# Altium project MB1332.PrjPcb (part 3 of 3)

## Sheet STLink_V3E_SWD.SchDoc: ST-LINK-V3E SWD
size A3; Date: Not used; ApprovedBy: Not used; CheckedBy: Not used; Author: Not used; CompanyName: STMicroelectronics; DrawnBy: Not used; Engineer: Not used; Organization: Not used; Address1: Not used; Address2: Not used; Address3: Not used; Address4: Not used; DocumentNumber: Not used; Revision: Not used; SheetNumber: 17; SheetTotal: 17
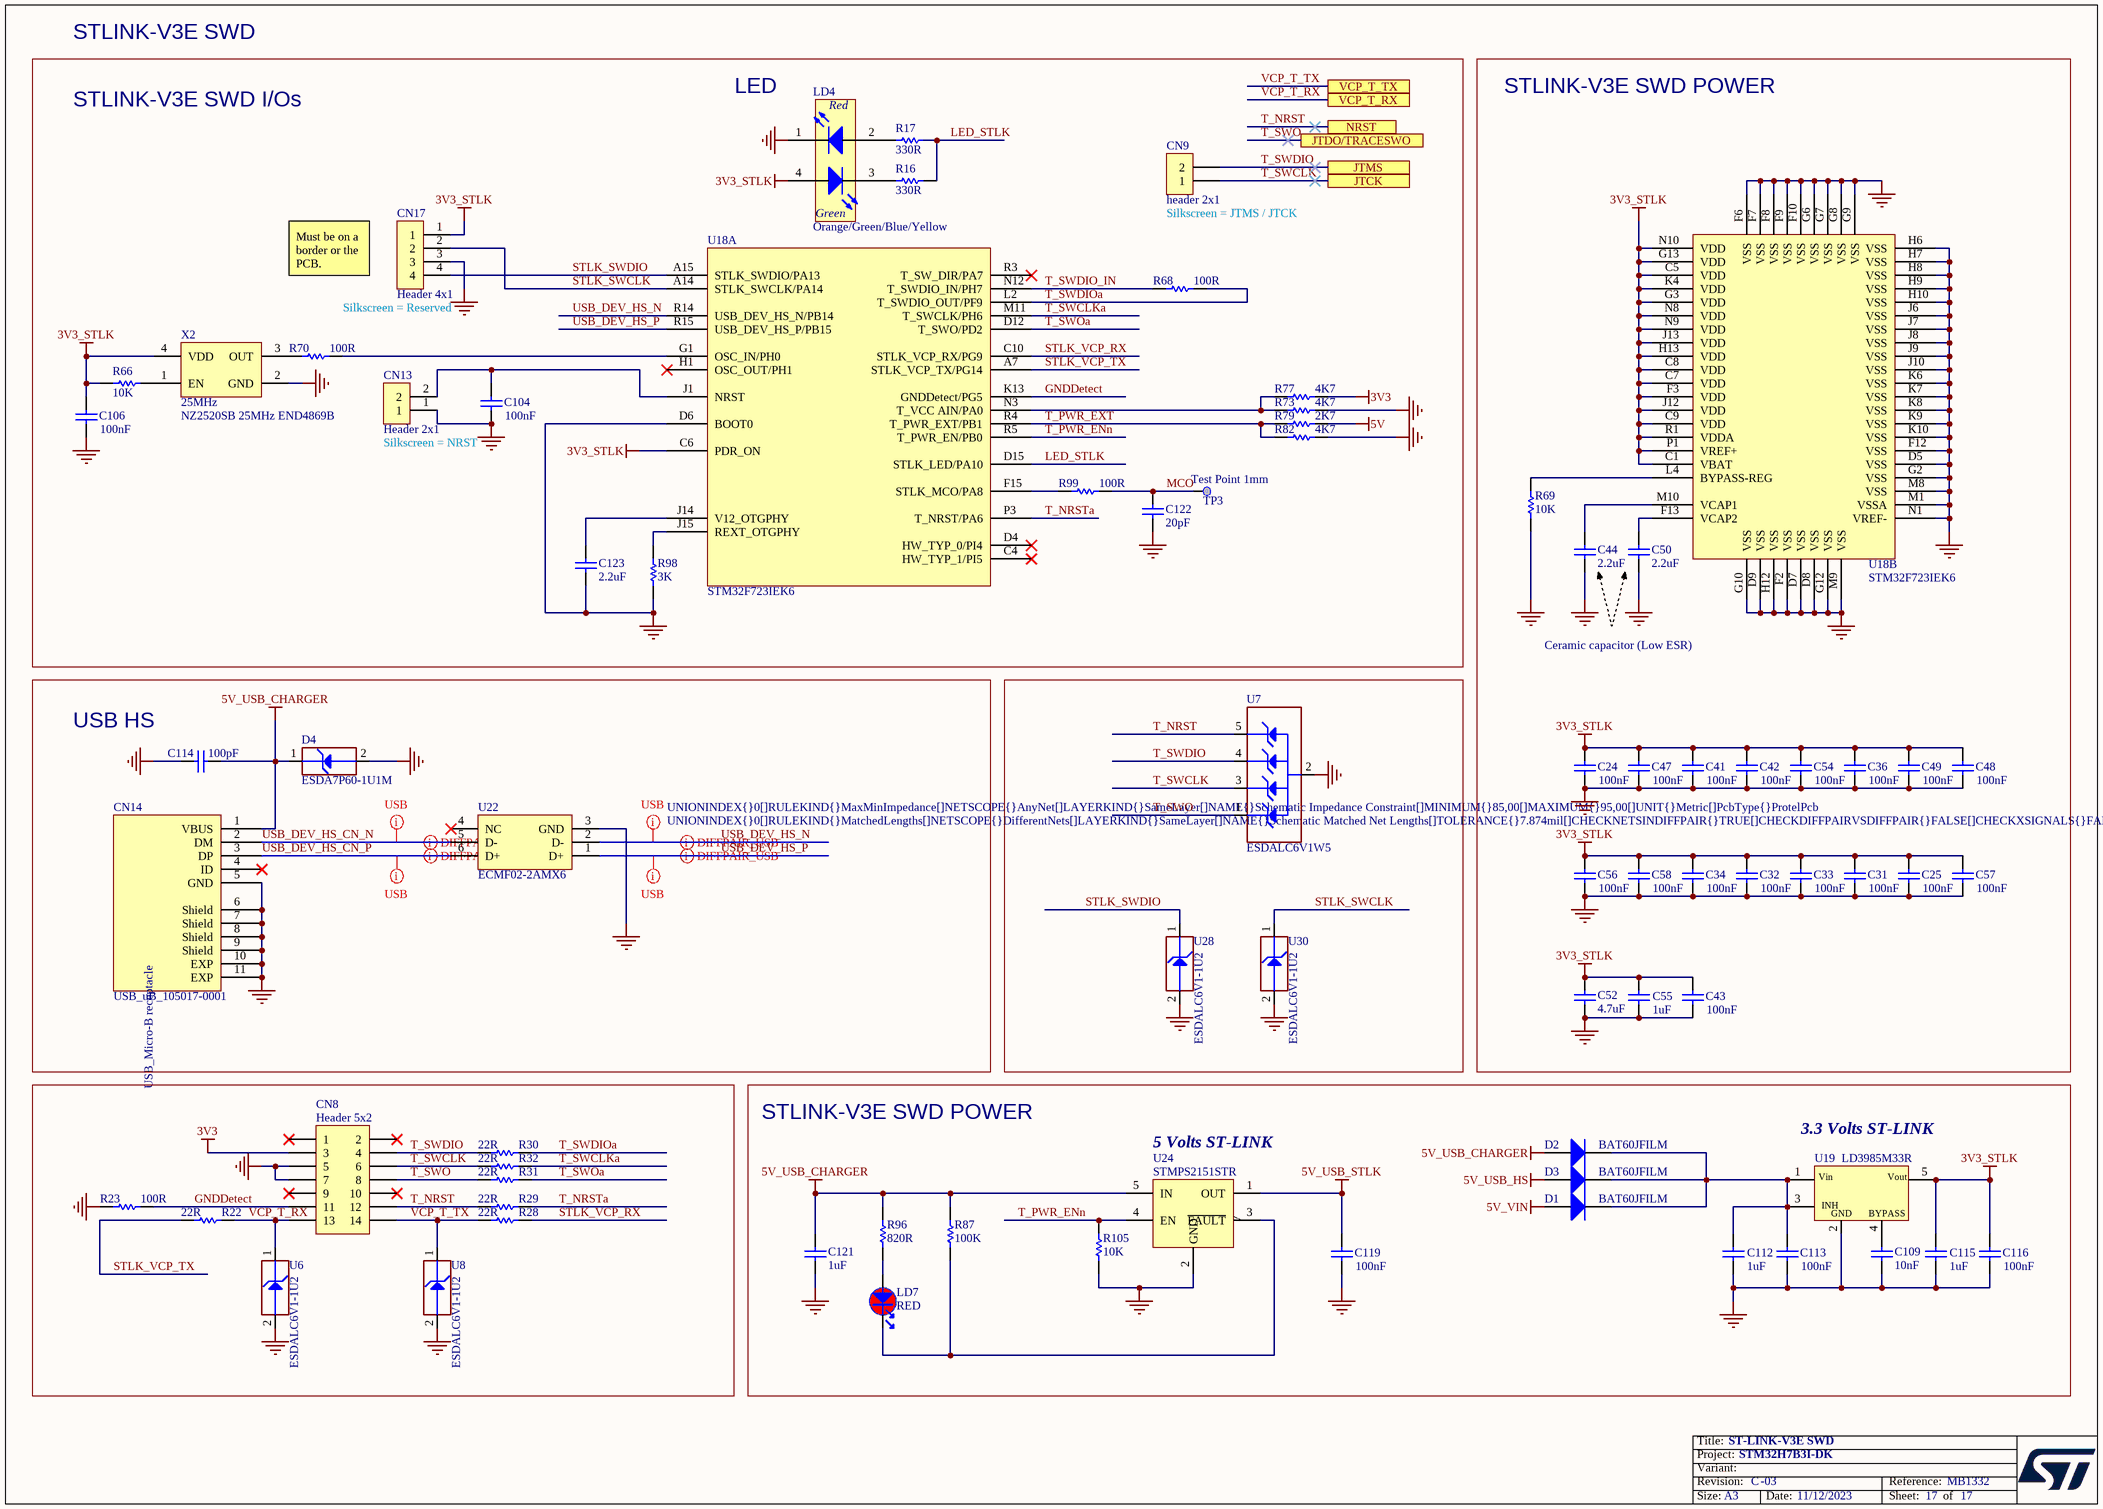
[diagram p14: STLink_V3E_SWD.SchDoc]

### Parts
C24  value 100nF  [C0402]  (hidden comment: Capacitor)
C25  value 100nF  [C0402]  (hidden comment: Capacitor)
C31  value 100nF  [C0402]  (hidden comment: Capacitor)
C32  value 100nF  [C0402]  (hidden comment: Capacitor)
C33  value 100nF  [C0402]  (hidden comment: Capacitor)
C34  value 100nF  [C0402]  (hidden comment: Capacitor)
C36  value 100nF  [C0402]  (hidden comment: Capacitor)
C41  value 100nF  [C0402]  (hidden comment: Capacitor)
C42  value 100nF  [C0402]  (hidden comment: Capacitor)
C43  value 100nF  [C0402]  (hidden comment: Capacitor)
C44  value 2.2uF  [C0603]  (hidden comment: Capacitor)
C47  value 100nF  [C0402]  (hidden comment: Capacitor)
C48  value 100nF  [C0402]  (hidden comment: Capacitor)
C49  value 100nF  [C0402]  (hidden comment: Capacitor)
C50  value 2.2uF  [C0603]  (hidden comment: Capacitor)
C52  value 4.7uF  [C0603]  (hidden comment: Capacitor)
C54  value 100nF  [C0402]  (hidden comment: Capacitor)
C55  value 1uF  [C0603]  (hidden comment: Capacitor)
C56  value 100nF  [C0402]  (hidden comment: Capacitor)
C57  value 100nF  [C0402]  (hidden comment: Capacitor)
C58  value 100nF  [C0402]  (hidden comment: Capacitor)
C104  value 100nF  [C0402]  (hidden comment: Capacitor)
C106  value 100nF  [C0402]  (hidden comment: Capacitor)
C109  value 10nF  [C0402]  (hidden comment: Capacitor)
C112  value 1uF  [C0603]  (hidden comment: Capacitor)
C113  value 100nF  [C0402]  (hidden comment: Capacitor)
C114  value 100pF  [C0402]  (hidden comment: Capacitor)
C115  value 1uF  [C0603]  (hidden comment: Capacitor)
C116  value 100nF  [C0402]  (hidden comment: Capacitor)
C119  value 100nF  [C0402]  (hidden comment: Capacitor)
C121  value 1uF  [C0603]  (hidden comment: Capacitor)
C122  value 20pF  [C0402]  (hidden comment: Capacitor)
C123  value 2.2uF  [C0603]  (hidden comment: Capacitor)
CN8  value Header 5x2  [CON_STDC14_Receiver_MEDIUM_WITH_MIPI10_3D]  (hidden comment: Header 7x2)
CN9  Header 2x1  [CON_988-JIUBABA_PHFS25-11-02-G0B115-T-1]
CN13  Header 2x1  [CON_SAMTEC_TSW-102-07-G-S]
CN14  value USB_uB_105017-0001  [CON_USBMICROB_MOLEX_105017-0001_H2P90]  (hidden comment: USB_uB_105017.0001)
CN17  Header 4x1  [CON_SAMTEC_TSW-104-07-G-S]
D1  BAT60JFILM  [DIO_SOD323]
D2  BAT60JFILM  [DIO_SOD323]
D3  BAT60JFILM  [DIO_SOD323]
D4  value ESDA7P60-1U1M  [ESD_QFN2_1P6X1_P125]  (hidden comment: ESD-TRANSIL)
LD4  value Orange/Green/Blue/Yellow  [LED_BI-GR_HSMF-A201-A00J1]  (hidden comment: LD_BICOLOR_CMS)
LD7  value RED  [LED_0603_VISHAY_VLMS1300-GS08_RED_1A2K_H0P8]  (hidden comment: LED_red)
R16  value 330R  [R0603]  (hidden comment: Resistor)
R17  value 330R  [R0603]  (hidden comment: Resistor)
R22  value 22R  [R0603]  (hidden comment: Resistor)
R23  value 100R  [R0402]  (hidden comment: Resistor)
R28  value 22R  [R0603]  (hidden comment: Resistor)
R29  value 22R  [R0603]  (hidden comment: Resistor)
R30  value 22R  [R0603]  (hidden comment: Resistor)
R31  value 22R  [R0603]  (hidden comment: Resistor)
R32  value 22R  [R0603]  (hidden comment: Resistor)
R66  value 10K  [R0402]  (hidden comment: Resistor)
R68  value 100R  [R0402]  (hidden comment: Resistor)
R69  value 10K  [R0402]  (hidden comment: Resistor)
R70  value 100R  [R0402]  (hidden comment: Resistor)
R73  value 4K7  [R0402]  (hidden comment: Resistor)
R77  value 4K7  [R0402]  (hidden comment: Resistor)
R79  value 2K7  [R0402]  (hidden comment: Resistor)
R82  value 4K7  [R0402]  (hidden comment: Resistor)
R87  value 100K  [R0402]  (hidden comment: Resistor)
R96  value 820R  [R0402]  (hidden comment: Resistor)
R98  value 3K  [R0402]  (hidden comment: Resistor)
R99  value 100R  [R0402]  (hidden comment: Resistor)
R105  value 10K  [R0402]  (hidden comment: Resistor)
TP3  value Test Point 1mm  [TP_SMD_1MM]  (hidden comment: Test Point)  (no BOM)
U6  value ESDALC6V1-1U2  [ESD_ST0201]  (hidden comment: ESD-TRANSIL)
U7  ESDALC6V1W5  [ESD_SOT323-5L]
U8  value ESDALC6V1-1U2  [ESD_ST0201]  (hidden comment: ESD-TRANSIL)
U18  value STM32F723IEK6  [ICC_UFBGA201_176+25_10X10_P065]  (hidden comment: ST-LINKV3E_SWD)  (parts A,B of 2)
U19  LD3985M33R  [REG_SOT23-5L]
U22  ECMF02-2AMX6  [ESD_QFN-6L_1P7X1P5_P050]
U24  STMPS2151STR  [MOS_SOT23-5L]
U28  value ESDALC6V1-1U2  [ESD_ST0201]  (hidden comment: ESD-TRANSIL)
U30  value ESDALC6V1-1U2  [ESD_ST0201]  (hidden comment: ESD-TRANSIL)
X2  value 25MHz  [OSC_NDK_NZ2520SB_4P]  (hidden comment: OSCILLATOR_4_PINS)

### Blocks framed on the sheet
STLINK-V3E SWD POWER: C24 C25 C31-C34 C36 C41-C44 C47-C50 C52 C54-C58 R69 U18
USB HS: C114 CN14 D4 U22
STLINK-V3E SWD POWER: C109 C112 C113 C115 C116 C119 C121 D1-D3 LD7 R87 R96 R105 U19 U24

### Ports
JTCK, JTDO/TRACESWO, JTMS, NRST, VCP_T_RX, VCP_T_TX

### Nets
3V3: CN8.3 R77.2
3V3_STLK: C24.1 C25.1 C31.1 C32.1 C33.1 C34.1 C36.1 C41.1 C42.1 C43.1 C47.1 C48.1 C49.1 C52.2 C54.1 C55.2 C56.1 C57.1 C58.1 C106.1 C115.2 C116.1 CN17.1 LD4.4(YellowGreen_anode) R66.1 U18.C1(VBAT) U18.C5(VDD) U18.C6(PDR_ON) U18.C7(VDD) U18.C8(VDD) U18.C9(VDD) U18.F3(VDD) U18.G3(VDD) U18.G13(VDD) U18.H13(VDD) U18.J12(VDD) U18.J13(VDD) U18.K4(VDD) U18.N8(VDD) U18.N9(VDD) U18.N10(VDD) U18.P1(VREF+) U18.R1(VDDA) U19.5(Vout) X2.4(VDD)
5V: R79.1
5V_USB_CHARGER: C114.2 C121.2 CN14.1(VBUS) D2.1(A) D4.1(IO1) R87.1 R96.2 U24.5(IN)
5V_USB_HS: D3.1(A)
5V_USB_STLK: C119.1 U24.1(OUT)
5V_VIN: D1.1(A)
GND: C24.2 C25.2 C31.2 C32.2 C33.2 C34.2 C36.2 C41.2 C42.2 C43.2 C44.1 C47.2 C48.2 C49.2 C50.1 C52.1 C54.2 C55.1 C56.2 C57.2 C58.2 C104.2 C106.2 C109.1 C112.1 C113.2 C114.1 C115.1 C116.2 C119.2 C121.1 C122.1 C123.1 CN8.5 CN8.7 CN13.1 CN14.5(GND) CN14.6(Shield) CN14.7(Shield) CN14.8(Shield) CN14.9(Shield) CN14.10(EXP) CN14.11(EXP) CN17.3 D4.2(GND) LD4.1(RED_cathode) R23.1 R69.1 R73.2 R82.1 R98.1 R105.2 U6.2(GND) U7.2(GND) U8.2(GND) U18.D5(VSS) U18.D6(BOOT0) U18.D7(VSS) U18.D8(VSS) U18.D9(VSS) U18.F2(VSS) U18.F6(VSS) U18.F7(VSS) U18.F8(VSS) U18.F9(VSS) U18.F10(VSS) U18.F12(VSS) U18.G2(VSS) U18.G6(VSS) U18.G7(VSS) U18.G8(VSS) U18.G9(VSS) U18.G10(VSS) U18.G12(VSS) U18.H6(VSS) U18.H7(VSS) U18.H8(VSS) U18.H9(VSS) U18.H10(VSS) U18.H12(VSS) U18.J6(VSS) U18.J7(VSS) U18.J8(VSS) U18.J9(VSS) U18.J10(VSS) U18.K6(VSS) U18.K7(VSS) U18.K8(VSS) U18.K9(VSS) U18.K10(VSS) U18.M1(VSSA) U18.M8(VSS) U18.M9(VSS) U18.N1(VREF-) U19.2(GND) U22.3(GND) U24.2(GND) U28.2(GND) U30.2(GND) X2.2(GND)
GNDDetect: CN8.11 R23.2 U18.K13(GNDDetect/PG5)
LED_STLK: R16.2 R17.2 U18.D15(STLK_LED/PA10)
MCO: C122.2 R99.2 TP3.1
STLK_SWCLK: CN17.2 U18.A14(STLK_SWCLK/PA14) U30.1(IO1)
STLK_SWDIO: CN17.4 U18.A15(STLK_SWDIO/PA13) U28.1(IO1)
STLK_VCP_RX: R28.2 U18.C10(STLK_VCP_RX/PG9)
STLK_VCP_TX: R22.2 U18.A7(STLK_VCP_TX/PG14)
T_NRST: CN8.12 R29.1 U7.5(IO4) ; port NRST
T_NRSTa: R29.2 U18.P3(T_NRST/PA6)
T_PWR_ENn: R105.1 U18.R5(T_PWR_EN/PB0) U24.4(EN)
T_PWR_EXT: R79.2 R82.2 U18.R4(T_PWR_EXT/PB1)
T_SWCLK: CN8.6 CN9.1 R32.1 U7.3(IO2) ; port JTCK
T_SWCLKa: R32.2 U18.M11(T_SWCLK/PH6)
T_SWDIO: CN8.4 CN9.2 R30.1 U7.4(IO3) ; port JTMS
T_SWDIO_IN: R68.1 U18.N12(T_SWDIO_IN/PH7)
T_SWDIOa: R30.2 R68.2 U18.L2(T_SWDIO_OUT/PF9)
T_SWO: CN8.8 R31.1 U7.1(IO1) ; port JTDO/TRACESWO
T_SWOa: R31.2 U18.D12(T_SWO/PD2)
USB_DEV_HS_CN_N: CN14.2(DM) U22.5(D-)
USB_DEV_HS_CN_P: CN14.3(DP) U22.6(D+)
USB_DEV_HS_N: U18.R14(USB_DEV_HS_N/PB14) U22.2(D-)
USB_DEV_HS_P: U18.R15(USB_DEV_HS_P/PB15) U22.1(D+)
VCP_T_RX: CN8.13 R22.1 U6.1(IO1) ; port VCP_T_RX
VCP_T_TX: CN8.14 R28.1 U8.1(IO1) ; port VCP_T_TX
NetC44_2: C44.2 U18.M10(VCAP1)
NetC50_2: C50.2 U18.F13(VCAP2)
NetC104_1: C104.1 CN13.2 U18.J1(NRST)
NetC109_2: C109.2 U19.4(BYPASS)
NetC112_2: C112.2 C113.1 D1.2(K) D2.2(K) D3.2(K) U19.1(Vin) U19.3(CE)
NetC123_2: C123.2 U18.J14(V12_OTGPHY)
NetLD4_2: LD4.2(Red_anode) R17.1
NetLD4_3: LD4.3(YellowGreen_cathode) R16.1
NetLD7_1: LD7.1 R96.1
NetLD7_2: LD7.2 R87.2 U24.3(~{FAULT})
NetR66_2: R66.2 X2.1(EN)
NetR69_2: R69.2 U18.L4(BYPASS-REG)
NetR70_1: R70.1 X2.3(OUT)
NetR70_2: R70.2 U18.G1(OSC_IN/PH0)
NetR73_1: R73.1 R77.1 U18.N3(T_VCC_AIN/PA0)
NetR98_2: R98.2 U18.J15(REXT_OTGPHY)
NetR99_1: R99.1 U18.F15(STLK_MCO/PA8)

Not connected (* = marked no-connect by the designer): CN8 1* 2* 9* 10*; CN14 4(ID)*; U18 C4(HW_TYP_1/PI5)* D4(HW_TYP_0/PI4)* H1(OSC_OUT/PH1)* R3(T_SW_DIR/PA7)*; U22 4(NC)*

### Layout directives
differential pair; rule Impedance Constraint [Min = 85.00    Max = 95.00    ]: USB_DEV_HS_CN_N, USB_DEV_HS_CN_P, USB_DEV_HS_N, USB_DEV_HS_P
rule Undefined; rule Matched Net Lengths [Tolerance = 0.2mm]; rule Impedance Constraint [Min = 85.00    Max = 95.00    ]: USB_DEV_HS_CN_N, USB_DEV_HS_CN_P, USB_DEV_HS_N, USB_DEV_HS_P

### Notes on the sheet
- STLINK-V3E SWD
- STLINK-V3E SWD I/Os
- LED
- (near CN9) Silkscreen = JTMS / JTCK
- Must be on a border or the PCB.
- Silkscreen = Reserved
- (near X2) NZ2520SB 25MHz END4869B
- Silkscreen = NRST
- Ceramic capacitor (Low ESR)
- (near U24) 5 Volts ST-LINK
- (near U19) 3.3 Volts ST-LINK

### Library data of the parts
C24 C25 C31-C34 C36 C41-C43 C47-C49 C54 C56-C58 C104 C106 C113 C116 C119 = MCD-00006: Capacitor, MLCC, 100nF, 16V, X7R, +/-10%, 0402, T=0.5mm; Manufacturer_Part_Number: CC0402KRX7R7BB104; Manufacturer: YAGEO; Part_Preference: Recommended; Partial_Alternate_Internal_Part_Number: MCD-03299; Component_Country_Of_Origin: China; ID: 2474; Order_Code_RS: 9402047; ShowFields: YES
C44 C50 C123 = MCD-00012: Capacitor, MLCC, 2.2uF, 10V, X5R, 10%, 0603, T=0,8mm; Manufacturer_Part_Number: CC0603KRX5R6BB225; Manufacturer: YAGEO; Alternate_Manufacturer_Part_Number: C0603C225K8PACTU; Alternate_Manufacturer: KEMET; BMS_Part_Number: 9142010; Part_Preference: Recommended; Partial_Alternate_Internal_Part_Number: MCD-00551; Provided_By: SUBCO; Component_Country_Of_Origin: China; ID: 2467; Order_Code_RS: 2370679; ShowFields: YES
C52 = MCD-00009: Capacitor, MLCC, 4.7uF, 16V, X5R, 10%, 0603, T=0.8mm; Manufacturer_Part_Number: CC0603KRX5R7BB475; Manufacturer: YAGEO; Part_Preference: Recommended; Partial_Alternate_Internal_Part_Number: MCD-03565; Provided_By: SUBCO; Alternate_EMS: A; Component_Country_Of_Origin: China; ID: 2471; ShowFields: YES
C55 C112 C115 C121 = MCD-00010: Capacitor, MLCC, 1uF, 16V, X5R, 10%, 0603, T=0,8mm; Manufacturer_Part_Number: CC0603KRX5R7BB105; Manufacturer: YAGEO; Part_Preference: Recommended; Provided_By: SUBCO; Component_Country_Of_Origin: China; ID: 2470; Order_Code_RS: 2370680; ShowFields: YES
C109 = MCD-00011: Capacitor, MLCC, 10nF, 16V, X7R, 10%, 0402, T=0.5mm; Manufacturer_Part_Number: CC0402KRX7R7BB103; Manufacturer: YAGEO; Part_Preference: Recommended; Provided_By: SUBCO; Component_Country_Of_Origin: China; ID: 2469; Order_Code_RS: 3019275; ShowFields: YES
C114 = MCD-00205: Capacitor, MLCC, 100pF, 50V, NPO, 5%, 0402, T=0,5mm; Manufacturer_Part_Number: CC0402JRNPO9BN101; Manufacturer: YAGEO; Part_Preference: Recommended; Provided_By: SUBCO; Component_Country_Of_Origin: China; ID: 2658; ShowFields: YES
C122 = MCD-00016: Capacitor, MLCC, 20pF, 50V, NPO, 5%, 0402, T=0,5mm; Manufacturer_Part_Number: CC0402JRNPO9BN200; Manufacturer: YAGEO; Part_Preference: Recommended; Provided_By: SUBCO; Component_Country_Of_Origin: China; ID: 2479; ShowFields: YES
CN8 = MCD-01226: Header 5x2, 1.27mm, Dual row, Straight, Surface mount, vertical male connector. 3.05mm lead. Mates with FFSD connector. Footprint compatible with FTSH-107-01-L-DV,-K,-A,-P,-ES (STDC14 MEDIUM); Manufacturer_Part_Number: FTSH-105-01-L-DV-K; Manufacturer: SAMTEC; Part_Preference: Recommended; Partial_Alternate_Internal_Part_Number: MCD-02956; Provided_By: SUBCO; Component_Country_Of_Origin: China, Costa Rica, Malaysia, USA, Vietnam; ID: 3265; Order_Code_RS: 159-2332; ShowFields: YES
CN9 = MCD-00314: Header, 2x1, 2.54mm, VR, TH, Height 6mm/3mm; Part_Type: Connector; Manufacturer_Part_Number: PHFS25-11-02-G0B115-T-1; Manufacturer: JIUBABA; Part_Preference: Alternate; Provided_By: SUBCO; Alternate_EMS: A; Component_Country_Of_Origin: Unknown; ID: 2554; ShowFields: YES
CN13 = MCD-00032: Header, 2x1, 2,54mm, VR, TH, Height 5.84mm/2.54mm; Part_Type: Connector; Manufacturer_Part_Number: TSW-102-07-G-S; Manufacturer: SAMTEC; Alternate_Manufacturer_Part_Number: 313102S111116; Alternate_Manufacturer: JIUBABA; Part_Preference: Recommended; Component_Country_Of_Origin: China, Costa Rica, Malaysia, USA, Vietnam; ID: 2484; Order_Code_RS: 2505044; ShowFields: YES
CN14 = MCD-00028: USB-MICRO-B, 0.65mm, RA, SMT, Bottom Mount,; Manufacturer_Part_Number: 1050170001; Manufacturer: MOLEX; Part_Type: Connector; Part_Preference: Recommended; Provided_By: SUBCO; Component_Country_Of_Origin: Unknown; ID: 2489; Order_Code_RS: 2293836; ShowFields: YES
CN17 = MCD-00029: Header, 4x1, 2,54mm, VR, TH, Height 5.84mm/2.54mm; Manufacturer_Part_Number: TSW-104-07-G-S; Manufacturer: SAMTEC; Part_Type: Connector; Part_Preference: Recommended; Component_Country_Of_Origin: China, Costa Rica, Malaysia, USA, Vietnam; ID: 2487; Order_Code_RS: 2667450; ShowFields: YES
D1-D3 = MCD-00034: Manufacturer: STMICROELECTRONICS; Part_Type: Diode; BMS_Part_Number: 9151097; Manufacturer_HQ_COO: EU; Part_Preference: Recommended; Provided_By: SUBCO with ST control; Component_Country_Of_Origin: China; ID: 2483; Order_Code_RS: 714-6879; ShowFields: YES
D4 = MCD-00251: High power transient voltage suppressor, 7V breakdown; Part_Type: Diode; Manufacturer: STMICROELECTRONICS; BMS_Part_Number: 9179042; Manufacturer_HQ_COO: EU; Part_Preference: Recommended; Provided_By: SUBCO with ST control; Component_Country_Of_Origin: China; ID: 2618; Order_Code_RS: 110-6381; ShowFields: YES
LD4 = MCD-02402: LED Multicolor, Orange/Green/Blue/Yellow, 2V, 20mA, 4-PLCC; Part_Type: Display; Manufacturer_Part_Number: 67-22SURSYGC/S530-A2/TR8; Manufacturer: EVERLIGHT; Part_Preference: Alternate; Full_Alternate_Internal_Part_Number: MCD-00051, MCD-02631; Alternate_EMS: C; ShowFields: YES; ID: 4508
LD7 = MCD-00587: LED Red, 0603 SMD, 2V Forward Voltage; Part_Type: Display; Manufacturer_Part_Number: VLMS1300-GS08; Manufacturer: VISHAY; Alternate_Manufacturer_Part_Number: LS Q976-NR-1; Alternate_Manufacturer: OSRAM OPTO SEMICONDUCTORS; Full_Alternate_Internal_Part_Number: MCD-02401; Part_Preference: Recommended; Provided_By: SUBCO; Component_Country_Of_Origin: China; ID: 3154; ShowFields: YES
R16 R17 = MCD-00197: Resistor,330R,0603,1%,1/10W; Manufacturer_Part_Number: RC0603FR-07330RL; Manufacturer: YAGEO; BMS_Part_Number: 9129729; Part_Preference: Recommended; Provided_By: SUBCO; Component_Country_Of_Origin: China; ID: 2672; ShowFields: YES
R22 R28-R32 = MCD-00066: Resistor,22R,0603,1%,1/10W; Manufacturer_Part_Number: RC0603FR-0722RL; Manufacturer: YAGEO; Part_Preference: Recommended; Provided_By: SUBCO; Component_Country_Of_Origin: China; ID: 2530; Order_Code_RS: 9238280; ShowFields: YES
R23 R68 R70 R99 = MCD-00067: Resistor, 100R, 0402, +/- 1%, 1/16W; Manufacturer_Part_Number: RC0402FR-07100RL; Manufacturer: YAGEO; Part_Preference: Recommended; Order_Code_RS: 9239111; Component_Country_Of_Origin: China; ShowFields: YES; ID: 2527
R66 R69 R105 = MCD-00053: Resistor,10K,0402,1%,1/16W; Manufacturer_Part_Number: RC0402FR-0710KL; Manufacturer: YAGEO; BMS_Part_Number: 9131590; Part_Preference: Recommended; Provided_By: SUBCO; Component_Country_Of_Origin: China; ID: 2539; Order_Code_RS: 9239359; ShowFields: YES
R73 R77 R82 = MCD-00065: Resistor,4K7,0402,1%,1/16W; Manufacturer_Part_Number: RC0402FR-074K7L; Manufacturer: YAGEO; Alternate_Manufacturer_Part_Number: RT0402FRE074K7L; Part_Preference: Recommended; Partial_Alternate_Internal_Part_Number: MCD-03300; Provided_By: SUBCO; Component_Country_Of_Origin: China; ID: 2526; Order_Code_RS: 9239316; ShowFields: YES
R79 = MCD-00055: Resistor,2K7,0402,1%,1/16W; Manufacturer_Part_Number: RC0402FR-072K7L; Manufacturer: YAGEO; Part_Preference: Recommended; Provided_By: SUBCO; Component_Country_Of_Origin: China; ID: 2535; Order_Code_RS: 9239286; ShowFields: YES
R87 = MCD-00059: Resistor,100K,0402,1%,1/16W; Manufacturer_Part_Number: RC0402FR-07100KL; Manufacturer: YAGEO; Alternate_Manufacturer_Part_Number: RT0402FRE07100KL; Part_Preference: Recommended; Partial_Alternate_Internal_Part_Number: MCD-03301; Provided_By: SUBCO; Component_Country_Of_Origin: China; ID: 2533; Order_Code_RS: 2421891; ShowFields: YES
R96 = MCD-00527: Resistor,820R,0402,1%,1/16W; Manufacturer_Part_Number: RC0402FR-07820RL; Manufacturer: YAGEO; Part_Preference: Recommended; Provided_By: SUBCO; Component_Country_Of_Origin: China; ID: 3217; ShowFields: YES
R98 = MCD-00185: Resistor,3K,0402,1%,1/16W; Manufacturer_Part_Number: RC0402FR-073KL; Manufacturer: YAGEO; Part_Preference: Recommended; Provided_By: SUBCO; Component_Country_Of_Origin: China; ID: 2682; ShowFields: YES
TP3 = MCD-00074: Test Point 1mm; Part_Type: Misc; Part_Preference: Recommended; Component_Country_Of_Origin: Unknown; ID: 2518; ShowFields: YES
U6 U8 U28 U30 = MCD-00170: ESD protection 6V1; Part_Type: Diode; Manufacturer: STMICROELECTRONICS; BMS_Part_Number: 9151132; Manufacturer_HQ_COO: EU; Part_Preference: Recommended; Provided_By: SUBCO with ST control; Component_Country_Of_Origin: China; ID: 2696; Order_Code_RS: 795-8404; ShowFields: YES
U7 = MCD-00136: Dual Transil array for ESD protection; Part_Type: Diode; Manufacturer: STMICROELECTRONICS; BMS_Part_Number: 9151112; Manufacturer_HQ_COO: EU; Part_Preference: Recommended; Provided_By: SUBCO with ST control; Component_Country_Of_Origin: China; ID: 2731; Order_Code_RS: 178-7373; ShowFields: YES
U18 = MCD-00596: STM32F723IEK  (STM32F7) BGA176; Part_Type: IC; Manufacturer: STMICROELECTRONICS; BMS_Part_Number: 9175300; Manufacturer_HQ_COO: EU; Part_Preference: Recommended; Provided_By: SUBCO with ST control; Component_Country_Of_Origin: Philippines; ID: 3144; Order_Code_RS: 135-8268; ShowFields: YES
U19 = MCD-00086: Ultra low drop-low noise BiCMOS voltage, regulators low ESR capacitors compatible; Manufacturer: STMICROELECTRONICS; Part_Type: IC; BMS_Part_Number: 9176161; Manufacturer_HQ_COO: EU; Part_Preference: Recommended; Provided_By: SUBCO with ST control; Component_Country_Of_Origin: China; ID: 2506; Order_Code_RS: 168-6500; ShowFields: YES
U22 = MCD-00649: Common mode filter with ESD protection for USB 2.0 interface; Part_Type: Diode; Manufacturer: STMICROELECTRONICS; BMS_Part_Number: 9151138; Manufacturer_HQ_COO: EU; Part_Preference: Recommended; Provided_By: SUBCO with ST control; Component_Country_Of_Origin: China; ID: 3094; Order_Code_RS: 880-5276; ShowFields: YES
U24 = MCD-00159: 500mA, Enhanced single channel power switches with active high enable pin; Part_Type: IC; Manufacturer: STMICROELECTRONICS; Alternate_Manufacturer_Part_Number: TPS2051C; Alternate_Manufacturer: TEXAS INSTRUMENTS; BMS_Part_Number: 9159009; Manufacturer_HQ_COO: EU; Part_Preference: Recommended; Provided_By: SUBCO with ST control; Component_Country_Of_Origin: Malaysia; ID: 2708; Order_Code_RS: 165-5516; ShowFields: YES
X2 = MCD-00597: Oscillator 25Mhz, +-50ppm, Vcc:3.3V typ, square wave: [0.1Vcc;0.9Vcc], Enable pin, SMD; Manufacturer_Part_Number: NZ2520SH-25MHZ-END4869C; Manufacturer: NDK; Alternate_Manufacturer_Part_Number: NZ2520SB 25MHz END4869B; Part_Type: Crystal_Osc; BMS_Part_Number: 9157050; Part_Preference: Recommended; Provided_By: SUBCO; Component_Country_Of_Origin: Unknown; ID: 3148; ShowFields: YES

## Sheet Power_Board.SchDoc: Board_Power
size A4; Date: Not used; ApprovedBy: Not used; CheckedBy: Not used; Author: Not used; CompanyName: STMicroelectronics; DrawnBy: Not used; Engineer: Not used; Organization: Not used; Address1: Not used; Address2: Not used; Address3: Not used; Address4: Not used; DocumentNumber: Not used; Revision: Not used; SheetNumber: 15; SheetTotal: 17
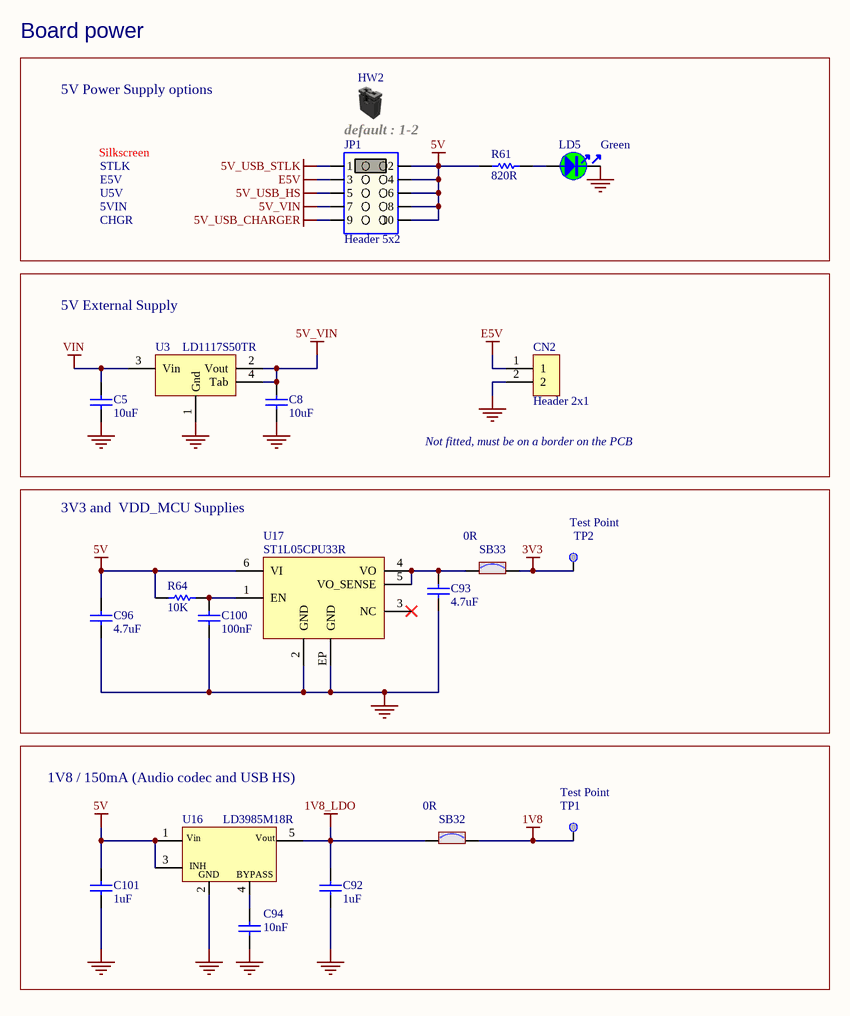
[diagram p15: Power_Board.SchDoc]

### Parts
C5  value 10uF  [C0805]  (hidden comment: Capacitor)
C8  value 10uF  [C0805]  (hidden comment: Capacitor)
C92  value 1uF  [C0402]  (hidden comment: Capacitor)
C93  value 4.7uF  [C0603]  (hidden comment: Capacitor)
C94  value 10nF  [C0402]  (hidden comment: Capacitor)
C96  value 4.7uF  [C0603]  (hidden comment: Capacitor)
C100  value 100nF  [C0402]  (hidden comment: Capacitor)
C101  value 1uF  [C0402]  (hidden comment: Capacitor)
CN2  Header 2x1  [CON_SAMTEC_TSW-102-07-G-S]
HW2  Shunt Black 2.54mm  (value not drawn)  (mechanical)
JP1  value Header 5x2  [CON_SAMTEC_TSM-105-01-L-DV]  (hidden comment: Jumper_Header 5x2 Fitted 1-2)
LD5  value Green  [LED_0603_VISHAY_VLMTG1300-GS08_GREEN_1A2K_H0P8]  (hidden comment: LED_green)
R61  value 820R  [R0603]  (hidden comment: Resistor)
R64  value 10K  [R0402]  (hidden comment: Resistor)
SB32  value 0R  [SOLDER-BRIDGE_R0603-0R]  (hidden comment: SB_ON)
SB33  value 0R  [SOLDER-BRIDGE_R0603-0R]  (hidden comment: SB_ON)
TP1  Test Point  [TP_SMD_2MM]  (no BOM)
TP2  Test Point  [TP_SMD_2MM]  (no BOM)
U3  LD1117S50TR  [REG_SOT223-TAB]
U16  LD3985M18R  [REG_SOT23-5L]
U17  ST1L05CPU33R  [ICC_DFN6-EPAD_3X3_P095]

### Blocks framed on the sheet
Board power: HW2 JP1 LD5 R61
5V External Supply: C5 C8 CN2 U3
3V3 and  VDD_MCU Supplies: C93 C96 C100 R64 SB33 TP2 U17
1V8 / 150mA (Audio codec and USB HS): C92 C94 C101 SB32 TP1 U16

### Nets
1V8: SB32.2 TP1.1
1V8_LDO: C92.2 SB32.1 U16.5(Vout)
3V3: SB33.2 TP2.1
5V: C96.2 C101.2 JP1.2 JP1.4 JP1.6 JP1.8 JP1.10 R61.1 R64.1 U16.1(Vin) U16.3(CE) U17.6(VI)
5V_USB_CHARGER: JP1.9
5V_USB_HS: JP1.5
5V_USB_STLK: JP1.1
5V_VIN: C8.2 JP1.7 U3.2(Vout) U3.4(Tab)
E5V: CN2.1 JP1.3
GND: C5.1 C8.1 C92.1 C93.1 C94.1 C96.1 C100.1 C101.1 CN2.2 LD5.2 U3.1(Gnd) U16.2(GND) U17.2(GND) U17.EP(GND)
VIN: C5.2 U3.3(Vin)
NetC93_2: C93.2 SB33.1 U17.4(VO) U17.5(VO_SENSE)
NetC94_2: C94.2 U16.4(BYPASS)
NetC100_2: C100.2 R64.2 U17.1(EN)
NetLD5_1: LD5.1 R61.2

Not connected (* = marked no-connect by the designer): U17 3(NC)*

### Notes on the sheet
- 5V Power Supply options
- Silkscreen
- default : 1-2
- STLK
- E5V
- U5V
- 5VIN
- CHGR
- Not fitted, must be on a border on the PCB

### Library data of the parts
C5 C8 = MCD-00014: Capacitor, MLCC, 10uF, 25V, X5R, 10%, 0805, T=0,85mm; Manufacturer_Part_Number: CC0805KRX5R8BB106; Manufacturer: YAGEO; Full_Alternate_Internal_Part_Number: MCD-02385; Part_Preference: Recommended; Partial_Alternate_Internal_Part_Number: MCD-03053; Provided_By: SUBCO; Component_Country_Of_Origin: China; ID: 2468; ShowFields: YES
C92 C101 = MCD-00095: Capacitor, MLCC, 1uF, 6V3, X5R, 10%, 0402, T=0,5mm; Manufacturer_Part_Number: GRM155R61E105KA12; Manufacturer: MURATA; Alternate_Manufacturer_Part_Number: GRM155R60J105KE19; Part_Preference: Recommended; Provided_By: SUBCO; Component_Country_Of_Origin: Japan°°; ID: 2772; Order_Code_RS: 2218855; ShowFields: YES
C93 C96 = MCD-00009: as C52 on sheet STLink_V3E_SWD
C94 = MCD-00011: as C109 on sheet STLink_V3E_SWD
C100 = MCD-00006: as C24 on sheet STLink_V3E_SWD
CN2 = MCD-00032: as CN13 on sheet STLink_V3E_SWD
HW2 = MCD-00043: SHUNT 2.54mm BLACK; Part_Type: Misc; Manufacturer: SAMTEC; Alternate_Manufacturer_Part_Number: 316102S111A; Alternate_Manufacturer: JIUBABA; Full_Alternate_Internal_Part_Number: MCD-02388; Manufacturer_HQ_COO: Unknown; Part_Preference: Recommended; Partial_Alternate_Internal_Part_Number: MCD-01849; Value: SNT-100-BK-G; Provided_By: SUBCO; Alternate_EMS: A; Component_Country_Of_Origin: China, Costa Rica, Malaysia, USA, Vietnam; ID: 2551; Order_Code_RS: 158-7784; ShowFields: YES
JP1 = MCD-01230: Header, 5x2, 2.54mm, VR, SMT, Height 5.84mm; Part_Type: Connector; Manufacturer_Part_Number: TSM-105-01-L-DV; Manufacturer: SAMTEC; Alternate_Manufacturer_Part_Number: PHFM25-1205G0B116T1; Alternate_Manufacturer: JIUBABA; BMS_Part_Number: 9183642; Part_Preference: Recommended; Provided_By: SUBCO; Component_Country_Of_Origin: China, Costa Rica, Malaysia, USA, Vietnam; ID: 3266; Order_Code_RS: 765-6506; ShowFields: YES
LD5 = MCD-00589: LED Green, 0603 SMD, Fw Voltage = 2.8V - 3.6V; Part_Type: Display; Manufacturer_Part_Number: VLMTG1300-GS08; Manufacturer: VISHAY; Alternate_Manufacturer_Part_Number: LG Q396-PS-35; Alternate_Manufacturer: OSRAM OPTO SEMICONDUCTORS; Part_Preference: Recommended; Order_Code_RS: 7730452; Provided_By: SUBCO; Component_Country_Of_Origin: China; ID: 3157; ShowFields: YES
R61 = MCD-00528: Resistor,820R,0603,1%,1/10W; Manufacturer_Part_Number: RC0603FR-07820RL; Manufacturer: YAGEO; BMS_Part_Number: 9129759; Part_Preference: Recommended; Provided_By: SUBCO; Component_Country_Of_Origin: China; ID: 3218; ShowFields: YES
R64 = MCD-00053: as R66 on sheet STLink_V3E_SWD
SB32 SB33 = MCD-00071: Solder Bridge ON; Part_Type: Resistor; Manufacturer_Part_Number: RC0603JR-070RL; Manufacturer: YAGEO; Manufacturer_HQ_COO: Unknown; Part_Preference: Recommended; Provided_By: SUBCO; Component_Country_Of_Origin: China; ID: 2521; Order_Code_RS: 199-5647; ShowFields: YES
TP1 TP2 = MCD-00177: Test Point 2mm; Part_Type: Misc; Part_Preference: Recommended; ID: 2690; ShowFields: YES
U3 = MCD-00088: IC REG LDO 5V 0.8A SOT223; Manufacturer: STMICROELECTRONICS; BMS_Part_Number: 9176133; Manufacturer_HQ_COO: EU; Part_Preference: Recommended; Provided_By: SUBCO with ST control; Component_Country_Of_Origin: China; ID: 2503; Order_Code_RS: 165-7748; ShowFields: YES
U16 = MCD-00078: Ultra low drop-low noise BiCMOS voltage, regulators low ESR capacitors compatible; Manufacturer: STMICROELECTRONICS; Part_Type: IC; BMS_Part_Number: 9176159; Manufacturer_HQ_COO: EU; Part_Preference: Recommended; Provided_By: SUBCO with ST control; Component_Country_Of_Origin: Malaysia; ID: 2516; Order_Code_RS: 686-8830; ShowFields: YES
U17 = MCD-01025: LDO, 3.3V, 1.3A, Very low quiescent current BiCMOS voltage regulator; Part_Type: IC; Manufacturer: STMICROELECTRONICS; BMS_Part_Number: 9176246; Manufacturer_HQ_COO: EU; Part_Preference: Recommended; Provided_By: SUBCO with ST control; Component_Country_Of_Origin: Malaysia; ID: 2998; ShowFields: YES

## Sheet Power_MCU.SchDoc: MCU_Power
size A4; Date: Not used; ApprovedBy: Not used; CheckedBy: Not used; Author: Not used; CompanyName: STMicroelectronics; DrawnBy: Not used; Engineer: Not used; Organization: Not used; Address1: Not used; Address2: Not used; Address3: Not used; Address4: Not used; DocumentNumber: Not used; Revision: Not used; SheetNumber: 14; SheetTotal: 17
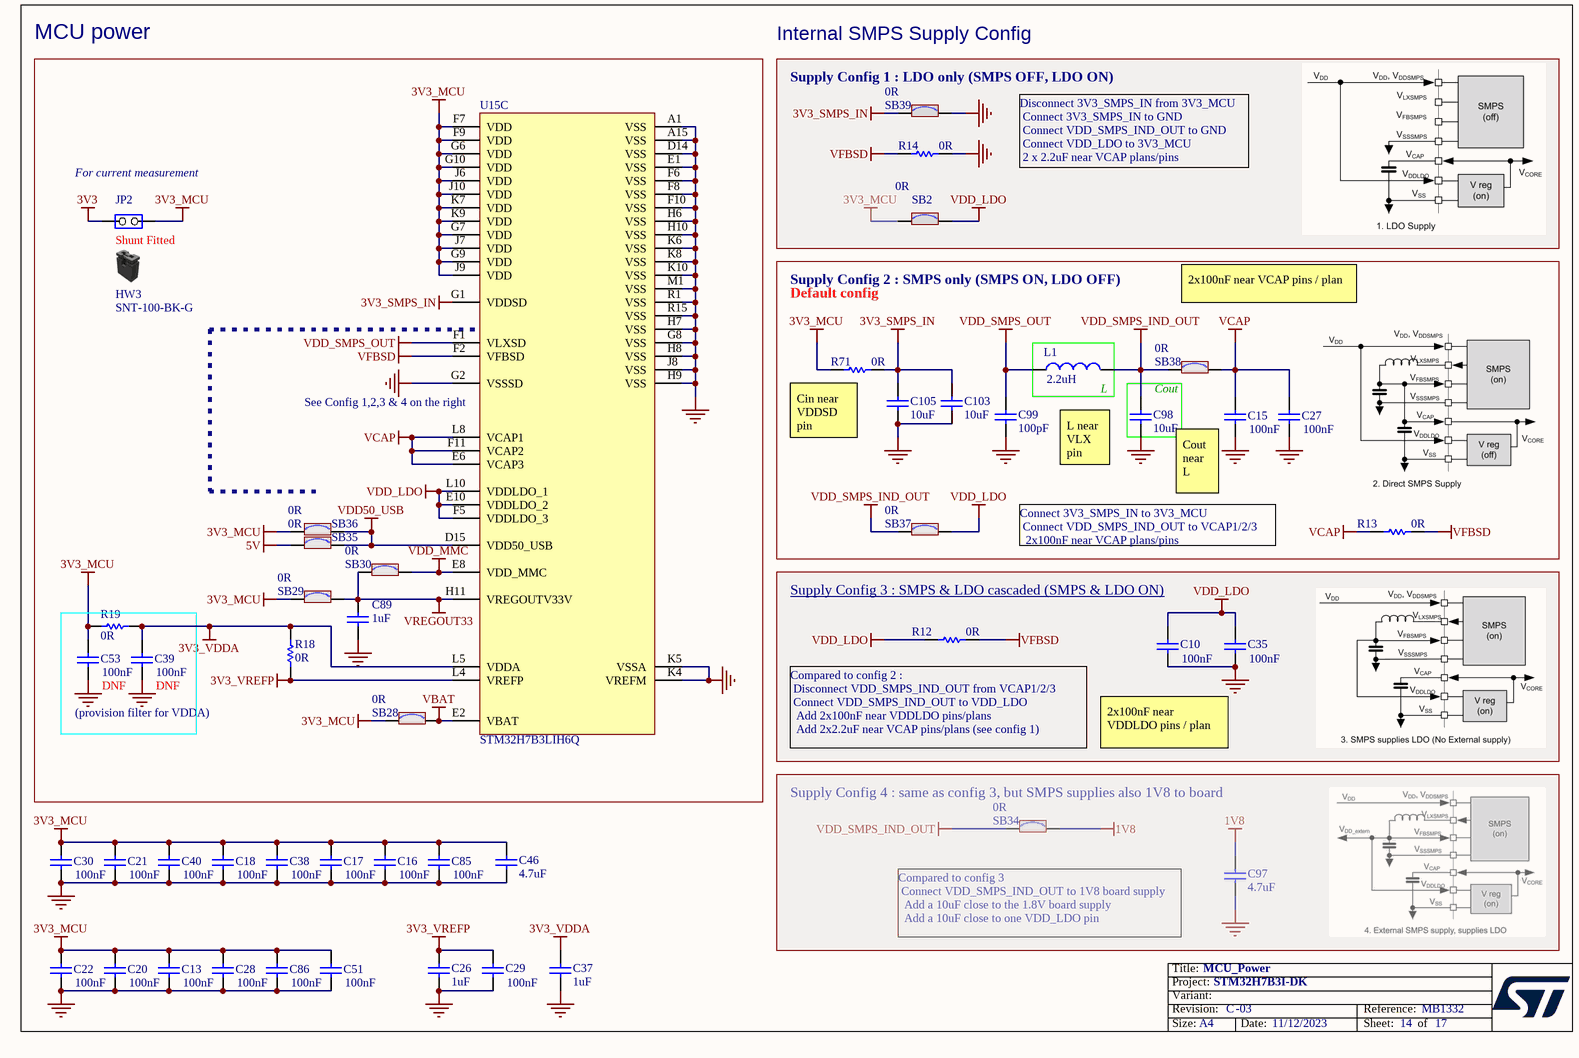
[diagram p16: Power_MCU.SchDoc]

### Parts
C10  value 100nF  [C0402]  (hidden comment: Capacitor)
C13  value 100nF  [C0402]  (hidden comment: Capacitor)
C15  value 100nF  [C0402]  (hidden comment: Capacitor)
C16  value 100nF  [C0402]  (hidden comment: Capacitor)
C17  value 100nF  [C0402]  (hidden comment: Capacitor)
C18  value 100nF  [C0402]  (hidden comment: Capacitor)
C20  value 100nF  [C0402]  (hidden comment: Capacitor)
C21  value 100nF  [C0402]  (hidden comment: Capacitor)
C22  value 100nF  [C0402]  (hidden comment: Capacitor)
C26  value 1uF  [C0402]  (hidden comment: Capacitor)
C27  value 100nF  [C0402]  (hidden comment: Capacitor)
C28  value 100nF  [C0402]  (hidden comment: Capacitor)
C29  value 100nF  [C0402]  (hidden comment: Capacitor)
C30  value 100nF  [C0402]  (hidden comment: Capacitor)
C35  value 100nF  [C0402]  (hidden comment: Capacitor)
C37  value 1uF  [C0402]  (hidden comment: Capacitor)
C38  value 100nF  [C0402]  (hidden comment: Capacitor)
C39  value 100nF  [C0402]  (hidden comment: Capacitor)
C40  value 100nF  [C0402]  (hidden comment: Capacitor)
C46  value 4.7uF  [C0603]  (hidden comment: Capacitor)
C51  value 100nF  [C0402]  (hidden comment: Capacitor)
C53  value 100nF  [C0402]  (hidden comment: Capacitor)
C85  value 100nF  [C0402]  (hidden comment: Capacitor)
C86  value 100nF  [C0402]  (hidden comment: Capacitor)
C89  value 1uF  [C0603]  (hidden comment: Capacitor)
C97  value 4.7uF  [C0603]  (hidden comment: Capacitor)
C98  value 10uF  [C0603]  (hidden comment: Capacitor)
C99  value 100pF  [C0402]  (hidden comment: Capacitor)
C103  value 10uF  [C0402]  (hidden comment: Capacitor)
C105  value 10uF  [C0402]  (hidden comment: Capacitor)
HW3  value SNT-100-BK-G  (hidden comment: Shunt Black 2.54mm)  (mechanical)
JP2  Jumper_Header 2x1  [CON_SAMTEC_TSW-102-07-G-S]  (value not drawn)
L1  value 2.2uH  [L0805_H0P9]  (hidden comment: Inductor)
R12  value 0R  [R0402]  (hidden comment: Resistor)
R13  value 0R  [R0402]  (hidden comment: Resistor)
R14  value 0R  [R0402]  (hidden comment: Resistor)
R18  value 0R  [R0603]  (hidden comment: Resistor)
R19  value 0R  [R0603]  (hidden comment: Resistor)
R71  value 0R  [R0603]  (hidden comment: Resistor)
SB2  value 0R  [SOLDER-BRIDGE_R0603-0R]  (hidden comment: SB_ON)
SB28  value 0R  [SOLDER-BRIDGE_R0603-0R]  (hidden comment: SB_ON)
SB29  value 0R  [SOLDER-BRIDGE_R0603-0R]  (hidden comment: SB_ON)
SB30  value 0R  [SOLDER-BRIDGE_R0603-0R]  (hidden comment: SB_ON)
SB34  value 0R  [SOLDER-BRIDGE_R0603-0R]  (hidden comment: SB_ON)
SB35  value 0R  [SOLDER-BRIDGE_R0603-0R]  (hidden comment: SB_ON)
SB36  value 0R  [SOLDER-BRIDGE_R0603-0R]  (hidden comment: SB_ON)
SB37  value 0R  [SOLDER-BRIDGE_R0603-0R]  (hidden comment: SB_ON)
SB38  value 0R  [SOLDER-BRIDGE_R0603-0R]  (hidden comment: SB_ON)
SB39  value 0R  [SOLDER-BRIDGE_R0603-0R]  (hidden comment: SB_ON)
U15  value STM32H7B3LIH6Q  [ICC_TFBGA225_13X13_STM32H7B3NIH6Q_P080]  (hidden comment: STM32H7B3NIH6Q)  (part C of 3)

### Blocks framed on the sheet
MCU power: C39 C53 C89 HW3 JP2 R18 R19 SB28-SB30 SB35 SB36 U15
Internal SMPS Supply Config: R14 SB2 SB39
L: L1
Cout: C98
Supply Config 3 : SMPS & LDO cascaded (SMPS & LDO ON): C10 C35 R12

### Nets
1V8: C97.2 SB34.1
3V3: JP2.1(COMMON)
3V3_MCU: C13.1 C16.1 C17.1 C18.1 C20.1 C21.1 C22.1 C28.1 C30.1 C38.1 C40.1 C46.2 C51.1 C53.1 C85.1 C86.1 JP2.2(NO) R19.1 R71.1 SB2.2 SB28.1 SB29.1 SB36.1 U15.F7(VDD) U15.F9(VDD) U15.G6(VDD) U15.G7(VDD) U15.G9(VDD) U15.G10(VDD) U15.J6(VDD) U15.J7(VDD) U15.J9(VDD) U15.J10(VDD) U15.K7(VDD) U15.K9(VDD)
3V3_SMPS_IN: C103.2 C105.2 R71.2 SB39.2 U15.G1(VDDSD)
3V3_VDDA: C37.2 C39.1 R18.1 R19.2 U15.L5(VDDA)
3V3_VREFP: C26.2 C29.2 R18.2 U15.L4(VREFP)
5V: SB35.1
GND: C10.1 C13.2 C15.2 C16.2 C17.2 C18.2 C20.2 C21.2 C22.2 C26.1 C27.2 C28.2 C29.1 C30.2 C35.1 C37.1 C38.2 C39.2 C40.2 C46.1 C51.2 C53.2 C85.2 C86.2 C89.1 C97.1 C98.1 C99.1 C103.1 C105.1 R14.2 SB39.1 U15.A1(VSS) U15.A15(VSS) U15.D14(VSS) U15.E1(VSS) U15.F6(VSS) U15.F8(VSS) U15.F10(VSS) U15.G2(VSSSD) U15.G8(VSS) U15.H6(VSS) U15.H7(VSS) U15.H8(VSS) U15.H9(VSS) U15.H10(VSS) U15.J8(VSS) U15.K4(VREFM) U15.K5(VSSA) U15.K6(VSS) U15.K8(VSS) U15.K10(VSS) U15.M1(VSS) U15.R1(VSS) U15.R15(VSS)
VBAT: SB28.2 U15.E2(VBAT)
VCAP: C15.1 C27.1 R13.1 SB38.1 U15.E6(VCAP3) U15.F11(VCAP2) U15.L8(VCAP1)
VDD50_USB: SB35.2 SB36.2 U15.D15(VDD50_USB)
VDD_LDO: C10.2 C35.2 R12.1 SB2.1 SB37.1 U15.E10(VDDLDO_2) U15.F5(VDDLDO_3) U15.L10(VDDLDO_1)
VDD_MMC: SB30.2 U15.E8(VDD_MMC)
VDD_SMPS_IND_OUT: C98.2 L1.2 SB34.2 SB37.2 SB38.2
VDD_SMPS_OUT: C99.2 L1.1 U15.F1(VLXSD)
VFBSD: R12.2 R13.2 R14.1 U15.F2(VFBSD)
VREGOUT33: C89.2 SB29.2 SB30.1 U15.H11(VREGOUTV33V)

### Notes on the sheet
- (near SB39) Supply Config 1 : LDO only (SMPS OFF, LDO ON)
- (near JP2) For current measurement
- Disconnect 3V3_SMPS_IN from 3V3_MCU
  Connect 3V3_SMPS_IN to GND
  Connect VDD_SMPS_IND_OUT to GND
  Connect VDD_LDO to 3V3_MCU
  2 x 2.2uF near VCAP plans/pins
- (near HW3) Shunt Fitted
- Default config
- Supply Config 2 : SMPS only (SMPS ON, LDO OFF)
- 2x100nF near VCAP pins / plan
- (near U15) See Config 1,2,3 & 4 on the right
- (near R71) Cin near VDDSD pin
- L near VLX pin
- (near C15) Cout near L
- Connect 3V3_SMPS_IN to 3V3_MCU
  Connect VDD_SMPS_IND_OUT to VCAP1/2/3
  2x100nF near VCAP plans/pins
- (provision filter for VDDA)
- DNF
- (near C39) DNF
- (near R12) Compared to config 2 :
  Disconnect VDD_SMPS_IND_OUT from VCAP1/2/3
  Connect VDD_SMPS_IND_OUT to VDD_LDO
  Add 2x100nF near VDDLDO pins/plans
  Add 2x2.2uF near VCAP pins/plans (see config 1)
- 2x100nF near VDDLDO pins / plan
- (near SB34) Supply Config 4 : same as config 3, but SMPS supplies also 1V8 to board
- Compared to config 3
  Connect VDD_SMPS_IND_OUT to 1V8 board supply
  Add a 10uF close to the 1.8V board supply
  Add a 10uF close to one VDD_LDO pin

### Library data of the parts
C10 C13 C15-C18 C20-C22 C27-C30 C35 C38-C40 C51 C53 C85 C86 = MCD-00006: as C24 on sheet STLink_V3E_SWD
C26 C37 = MCD-01722: Capacitor, 1uF, 10V, X5R, 10%, 0402, T=0.5mm; Manufacturer_Part_Number: CC0402KRX5R6BB105; Manufacturer: YAGEO; Part_Preference: Recommended; Provided_By: SUBCO; Component_Country_Of_Origin: China; ID: 3822; ShowFields: YES
C46 = MCD-00009: as C52 on sheet STLink_V3E_SWD
C89 = MCD-00010: as C55 on sheet STLink_V3E_SWD
C97 = MCD-01121: Capacitor, MLCC, 4.7uF, 10V, X5R, +/-20%, 0603, T=0.8mm; Manufacturer_Part_Number: GRM188R61A475ME15; Manufacturer: MURATA; Part_Preference: Forbidden; Full_Alternate_Internal_Part_Number: MCD-03342; Component_Country_Of_Origin: Japan; ShowFields: YES; ID: 3375
C98 = MCD-00243: Capacitor, MLCC, 10uF, 6V3, X5R, 10%, 0603, T=0,8mm; Manufacturer_Part_Number: CC0603KRX5R5BB106; Manufacturer: YAGEO; Part_Preference: Recommended; Provided_By: SUBCO; Component_Country_Of_Origin: China; ID: 2626; ShowFields: YES
C99 = MCD-00205: as C114 on sheet STLink_V3E_SWD
C103 C105 = MCD-01716: Capacitor, MLCC, 10uF, 6V3, X5R, 20%, 0402, T=0.5mm; Manufacturer_Part_Number: CC0402MRX5R5BB106; Manufacturer: YAGEO; Part_Preference: Recommended; Provided_By: SUBCO; Component_Country_Of_Origin: China; ID: 3816; ShowFields: YES
HW3 = MCD-00043: SHUNT 2.54mm BLACK; Manufacturer: SAMTEC; Part_Type: Misc; Alternate_Manufacturer_Part_Number: 316102S111A; Alternate_Manufacturer: JIUBABA; Full_Alternate_Internal_Part_Number: MCD-02388; Manufacturer_HQ_COO: Unknown; Part_Preference: Recommended; Partial_Alternate_Internal_Part_Number: MCD-01849; Provided_By: SUBCO; Alternate_EMS: A; Component_Country_Of_Origin: China, Costa Rica, Malaysia, USA, Vietnam; ID: 2551; Order_Code_RS: 158-7784; ShowFields: YES
JP2 = MCD-00045: Header, 2x1, 2,54mm, VR, TH, Height 5.84mm/2.54mm; Manufacturer_Part_Number: TSW-102-07-G-S; Manufacturer: SAMTEC; Part_Type: Connector; Alternate_Manufacturer_Part_Number: 313102S111116; Alternate_Manufacturer: JIUBABA; Full_Alternate_Internal_Part_Number: MCD-02390; Part_Preference: Recommended; Partial_Alternate_Internal_Part_Number: MCD-02957, MCD-03720; Provided_By: SUBCO; Component_Country_Of_Origin: China, Costa Rica, Malaysia, USA, Vietnam; ID: 2545; Order_Code_RS: 2505044; ShowFields: YES
L1 = MCD-01340: Inductor, 2.2uH, 20%, Isat 1.2A, DCR 0.228Ohm, 0805; Manufacturer_Part_Number: DFE201210U-2R2M=P2; Manufacturer: MURATA; Part_Preference: Recommended; Provided_By: SUBCO; Component_Country_Of_Origin: Japan°°; ID: 3440; ShowFields: YES
R12-R14 = MCD-00052: Resistor,0R,0402,5%,1/16W; Manufacturer_Part_Number: RC0402JR-070RL; Manufacturer: YAGEO; Part_Preference: Recommended; Provided_By: SUBCO; Component_Country_Of_Origin: China; ID: 2540; Order_Code_RS: 9232516RL; ShowFields: YES
R18 R19 R71 = MCD-00056: Resistor,0R,0603,5%,1/10W; Manufacturer_Part_Number: RC0603JR-070RL; Manufacturer: YAGEO; Part_Preference: Recommended; Provided_By: SUBCO; Component_Country_Of_Origin: China; ID: 2536; Order_Code_RS: 9233130RL; ShowFields: YES
SB2 SB28-SB30 SB34-SB39 = MCD-00071: as SB32 on sheet Power_Board
U15 = MCD-01929: MCU, ARM Cortex-M7 32-bit, 2MB Flash, 1.4MB RAM, With Crypto, SMPS; Part_Type: IC; Manufacturer: STMICROELECTRONICS; BMS_Part_Number: 9175358; Part_Preference: Recommended; Manufacturer_HQ_COO: EU; Order_Code_RS: 201-4447; Component_Country_Of_Origin: Philippines; ShowFields: YES; ID: 4029

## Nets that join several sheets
1V8: Audio_Codec (8 pins), Peripherals (U5.2), USB_OTG_HS_externalPHY (C108.1 U20.28 U20.30), Power_Board (SB32.2 TP1.1), Power_MCU (C97.2 SB34.1)
3V3: Audio_Codec (R55.2 R56.2 SB20.1), Camera (C63.2 C64.2 CN7.20 CN7.30), FDCAN (C59.1 U4.5), LCD (C1.1 CN1.50), Memory (15 pins), OCSPI (8 pins), Peripherals (8 pins), SDcard (8 pins), USB_OTG_HS_externalPHY (10 pins), MCU (R51.1 SW1.2), Arduino (CN19.2 CN19.4 R1.2), JTAG (CN12.1), STLink_V3E_SWD (CN8.3 R77.2), Power_Board (SB33.2 TP2.1), Power_MCU (JP2.1)
3V3_VREFP: Arduino (C79.1 R45.2), Power_MCU (C26.2 C29.2 R18.2 U15.L4)
5V: FDCAN (C45.1 U4.3), LCD (R3.1), Peripherals (P1.6 P1.15 U5.42), USB_OTG_HS_externalPHY (C117.1 U20.21 U25.5), Arduino (CN19.5), STLink_V3E_SWD (R79.1), Power_Board (12 pins), Power_MCU (SB35.1)
5V_USB_CHARGER: STLink_V3E_SWD (8 pins), Power_Board (JP1.9)
5V_USB_HS: USB_OTG_HS_externalPHY (R84.2), STLink_V3E_SWD (D3.1), Power_Board (JP1.5)
5V_USB_STLK: STLink_V3E_SWD (C119.1 U24.1), Power_Board (JP1.1)
5V_VIN: Arduino (R114.2), STLink_V3E_SWD (D1.1), Power_Board (C8.2 JP1.7 U3.2 U3.4)
GND: Audio_Codec (27 pins), Camera (7 pins), FDCAN (5 pins), LCD (13 pins), Memory (15 pins), OCSPI (6 pins), Peripherals (15 pins), SDcard (11 pins), USB_OTG_HS_externalPHY (27 pins), MCU (12 pins), Arduino (6 pins), JTAG (CN12.3 CN12.5 U11.2 U12.2), STLink_V3E_SWD (100 pins), Power_Board (14 pins), Power_MCU (55 pins)
VIN: Arduino (CN19.8), Power_Board (C5.2 U3.3)
2_CTS: Peripherals (SB6.1 SB25.2), MCU (SB31.1 U15.P1)
2_RTS: Peripherals (SB13.1 SB23.2), MCU (U15.A11)
2_RX: Peripherals (SB11.1 SB21.2), MCU (U15.B10)
2_TX: Peripherals (SB9.1 SB18.2), MCU (U15.C10)
A0: Memory (U14.H7), MCU (U15.G4)
A1: Memory (U14.H8), MCU (U15.G3)
A2: Memory (U14.J8), MCU (U15.H1)
A3: Memory (U14.J7), MCU (U15.J1)
A4: Memory (U14.J3), MCU (U15.H3)
A5: Memory (U14.J2), MCU (U15.J2)
A6: Memory (U14.H3), MCU (U15.R9)
A7: Memory (U14.H2), MCU (U15.M8)
A8: Memory (U14.H1), MCU (U15.P9)
A9: Memory (U14.G3), MCU (U15.N9)
A10: Memory (U14.H9), MCU (U15.R10)
A11: Memory (U14.G2), MCU (U15.P10)
A14: Memory (U14.G7), MCU (U15.H12)
A15: Memory (U14.G8), MCU (U15.G14)
ARD_A0: MCU (SB45.2), Arduino (CN20.1)
ARD_A1: MCU (U15.M6), Arduino (CN20.2)
ARD_A2: MCU (U15.P3), Arduino (CN20.3)
ARD_A3: MCU (U15.R3), Arduino (CN20.4)
ARD_A4: MCU (U15.N1), Arduino (SB52.1)
ARD_A5: MCU (U15.N2), Arduino (SB54.1)
ARD_D0: MCU (U15.B15), Arduino (CN11.1)
ARD_D1: MCU (U15.D13), Arduino (CN11.2)
ARD_D2: MCU (U15.E3), Arduino (CN11.3)
ARD_D3: MCU (U15.N13), Arduino (CN11.4)
ARD_D4: MCU (U15.E5), Arduino (CN11.5)
ARD_D5: MCU (U15.P15), Arduino (CN11.6)
ARD_D6: MCU (U15.M12), Arduino (CN11.7)
ARD_D7: MCU (U15.F3), Arduino (CN11.8)
ARD_D8: MCU (U15.M3), Arduino (CN10.1)
ARD_D9: MCU (U15.D4), Arduino (CN10.2)
ARD_D10: MCU (U15.C13), Arduino (CN10.3)
AUDIO_NRST: Audio_Codec (R44.2 U13.25), MCU (U15.G15)
CKOUT: Peripherals (CN3.3 CN3.4), MCU (SB50.2)
D0: Memory (U14.A8), MCU (U15.K12)
D1: Memory (U14.B9), MCU (U15.K13)
D2: Memory (U14.B8), MCU (U15.C11)
D3: Memory (U14.C9), MCU (U15.A12)
D4: Memory (U14.C8), MCU (U15.M9)
D5: Memory (U14.D9), MCU (U15.R11)
D6: Memory (U14.D8), MCU (U15.P11)
D7: Memory (U14.E9), MCU (U15.N11)
D8: Memory (U14.E1), MCU (U15.R12)
D9: Memory (U14.D2), MCU (U15.L9)
D10: Memory (U14.D1), MCU (U15.M10)
D11: Memory (U14.C2), MCU (U15.N10)
D12: Memory (U14.C1), MCU (U15.P12)
D13: Memory (U14.B2), MCU (U15.L12)
D14: Memory (U14.B1), MCU (U15.N15)
D15: Memory (U14.A2), MCU (U15.L13)
DCMI_D0: Camera (CN7.4), Peripherals (P1.11), MCU (U15.F14)
DCMI_D1: Camera (CN7.5), Peripherals (CN3.7 P1.17), MCU (U15.E15)
DCMI_D2: Camera (CN7.6), MCU (U15.A8)
DCMI_D3: Camera (CN7.7), SDcard (CN4.8 R9.1 U10.5 U10.6), MCU (U15.E14)
DCMI_D4: Camera (CN7.8), SDcard (CN4.2 R6.1 U9.2 U9.9), MCU (U15.D11)
DCMI_D5: Camera (CN7.9), Peripherals (P1.18), MCU (U15.D10)
DCMI_D6: Camera (CN7.10), Peripherals (P1.20), MCU (U15.B4)
DCMI_D7: Camera (CN7.11), Peripherals (CN3.5 P1.19), MCU (U15.A3)
DCMI_HSYNC: Camera (CN7.17), MCU (SB44.1 SB45.1 U15.L6)
DCMI_PIXCLK: Camera (CN7.15), MCU (U15.P5)
DCMI_PWR_EN: Camera (CN7.25), MCU (U15.R5)
DCMI_VSYNC: Camera (CN7.19), MCU (U15.D6)
DETECTn: Peripherals (CN3.10), MCU (U15.C3)
DFSDM1_2_DATIN1: Peripherals (CN3.6), MCU (SB48.2)
EXT_RESET: Peripherals (CN16.5), MCU (U15.A4)
FDCAN_RX: FDCAN (U4.4), MCU (SB3.1)
FDCAN_STBY: FDCAN (R20.1 U4.8), MCU (SB5.1)
FDCAN_TX: FDCAN (U4.1), MCU (SB4.1)
FMC_NBL0: Memory (U14.E8), MCU (U15.B3)
FMC_NBL1: Memory (U14.F1), MCU (U15.C4)
I2C4_SCL: Audio_Codec (R56.1 U13.3), Camera (CN7.28), LCD (CN1.40), MCU (U15.L15)
I2C4_SDA: Audio_Codec (R55.1 U13.2), Camera (CN7.27), LCD (CN1.38), MCU (U15.K11)
I2S6_CK: Audio_Codec (R52.2), MCU (U15.D8)
I2S6_MCK: Audio_Codec (R48.2), MCU (SB46.2)
I2S6_SDI: Audio_Codec (R47.2), MCU (U15.C8)
I2S6_SDO: Audio_Codec (R60.2), MCU (U15.A7)
I2S6_WS: Audio_Codec (R54.2), MCU (SB31.2)
JTDI: MCU (U15.C12), JTAG (R36.2)
LCD_B0: LCD (CN1.21), MCU (U15.E9)
LCD_B1: LCD (CN1.23), MCU (U15.D9)
LCD_B2: LCD (CN1.25), MCU (U15.C9)
LCD_B3: LCD (CN1.27), MCU (U15.B9)
LCD_B4: LCD (CN1.29), MCU (U15.B7)
LCD_B5: LCD (CN1.31), MCU (U15.C7)
LCD_B6: LCD (CN1.33), MCU (U15.A6)
LCD_B7: LCD (CN1.35), MCU (U15.B6)
LCD_BL_CTRL: LCD (CN1.43), MCU (U15.P2)
LCD_CLK: LCD (CN1.32), MCU (U15.H4)
LCD_DE: LCD (CN1.22), MCU (U15.D7)
LCD_G0: LCD (CN1.4), MCU (U15.K15)
LCD_G1: LCD (CN1.6), MCU (U15.J15)
LCD_G2: LCD (CN1.8), MCU (U15.J14)
LCD_G3: LCD (CN1.10), MCU (U15.J13)
LCD_G4: LCD (CN1.12), MCU (U15.J11)
LCD_G5: LCD (CN1.14), MCU (U15.J12)
LCD_G6: LCD (CN1.16), MCU (U15.H15)
LCD_G7: LCD (CN1.18), MCU (U15.H14)
LCD_HSYNC: LCD (CN1.26), MCU (U15.H2)
LCD_INT: LCD (CN1.39), MCU (U15.M4)
LCD_ON/OFF: LCD (CN1.24), MCU (U15.R2)
LCD_R0: LCD (CN1.3), MCU (U15.M7)
LCD_R1: LCD (CN1.5), MCU (U15.N7)
LCD_R2: LCD (CN1.7), MCU (U15.P7)
LCD_R3: LCD (CN1.9), MCU (U15.R7)
LCD_R4: LCD (CN1.11), MCU (U15.R8)
LCD_R5: LCD (CN1.13), MCU (U15.P8)
LCD_R6: LCD (CN1.15), MCU (U15.N12)
LCD_R7: LCD (CN1.17), MCU (U15.K14)
LCD_VSYNC: LCD (CN1.28), MCU (U15.H5)
MCO1: Camera (R25.1), MCU (U15.G11)
MEMS_LED: Peripherals (CN3.12), MCU (U15.B14)
MISO: Peripherals (SB10.1 SB19.1), MCU (U15.J5)
MOSI: Peripherals (SB8.1 SB26.1), MCU (U15.N3)
NJTRST: MCU (U15.B5), JTAG (R39.2)
nSS: Peripherals (SB7.1 SB24.1), MCU (SB3.2 U15.C15)
OCSPI1_CLK: OCSPI (U27.B2), MCU (R111.1)
OCSPI1_DQS: OCSPI (U27.C3), MCU (R91.1)
OCSPI1_IO0: OCSPI (U27.D3), MCU (R106.2)
OCSPI1_IO1: OCSPI (U27.D2), MCU (R109.2)
OCSPI1_IO2: OCSPI (U27.C4), MCU (R92.2)
OCSPI1_IO3: OCSPI (U27.D4), MCU (R94.2)
OCSPI1_IO4: OCSPI (U27.D5), MCU (R93.1)
OCSPI1_IO5: OCSPI (U27.E3), MCU (R107.1)
OCSPI1_IO6: OCSPI (U27.E2), MCU (R108.1)
OCSPI1_IO7: OCSPI (U27.E1), MCU (R110.2)
OCSPI1_NCS: OCSPI (R113.2 U27.C2), MCU (R112.1)
OSC_24M: Camera (R26.1), USB_OTG_HS_externalPHY (SB41.2)
PA12: Peripherals (SB12.1 SB22.1), MCU (SB4.2 U15.C14)
PH8: Peripherals (P1.12), MCU (SB5.2 U15.P14)
PMOD8-MOSIs: Peripherals (P1.8), MCU (U15.M15)
PMOD9: Peripherals (P1.9), MCU (U15.M14)
PMOD13-ADC: Peripherals (P1.13), MCU (SB44.2)
PMOD14-PWM: Peripherals (P1.14), MCU (U15.K1)
SAI1_FS_A: Audio_Codec (R53.2), MCU (U15.C2)
SAI1_MCLK_A: Audio_Codec (R49.2), MCU (U15.G12)
SAI1_SCK_A: Audio_Codec (R50.2), MCU (U15.D3)
SAI1_SD_A: Audio_Codec (R59.2), MCU (U15.E4)
SAI1_SD_B: Audio_Codec (R46.2), MCU (U15.B1)
SDCKE1: Memory (R67.2), MCU (U15.R14)
SDCLK: Memory (U14.F2), MCU (U15.F15)
SDIO1_CK: SDcard (CN4.5 U10.2 U10.9), MCU (U15.B12)
SDIO1_CMD: SDcard (CN4.3 R7.1 U10.1 U10.10), MCU (U15.B11)
SDIO1_D0: SDcard (CN4.7 R8.1 U10.4 U10.7), MCU (U15.F13)
SDIO1_D2: SDcard (CN4.1 R5.1 U9.1 U9.10), MCU (U15.A13)
SDNCAS: Memory (U14.F7), MCU (U15.A5)
SDNE1: Memory (U14.G9), MCU (U15.M11)
SDNRAS: Memory (U14.F8), MCU (U15.N8)
SDNWE: Memory (U14.F9), MCU (U15.P4)
T_NRST: Camera (CN7.26), LCD (CN1.36), OCSPI (SB51.1), Peripherals (SB15.2), USB_OTG_HS_externalPHY (SB40.2), MCU (5 pins), Arduino (CN19.3), JTAG (R38.2), STLink_V3E_SWD (CN8.12 R29.1 U7.5)
T_SWCLK: MCU (U15.B13), JTAG (R41.2), STLink_V3E_SWD (CN8.6 CN9.1 R32.1 U7.3)
T_SWDIO: MCU (U15.E12), JTAG (R40.2), STLink_V3E_SWD (CN8.4 CN9.2 R30.1 U7.4)
T_SWO: MCU (U15.C6), JTAG (R37.2), STLink_V3E_SWD (CN8.8 R31.1 U7.1)
ULPI_CK: USB_OTG_HS_externalPHY (U20.1), MCU (U15.N5)
ULPI_D0: USB_OTG_HS_externalPHY (U20.3), MCU (SB46.1 U15.R4)
ULPI_D1: USB_OTG_HS_externalPHY (U20.4), MCU (SB47.2)
ULPI_D2: USB_OTG_HS_externalPHY (U20.5), MCU (U15.L7)
ULPI_D3: USB_OTG_HS_externalPHY (U20.6), MCU (U15.R13)
ULPI_D4: USB_OTG_HS_externalPHY (U20.7), MCU (U15.P13)
ULPI_D5: USB_OTG_HS_externalPHY (U20.9), MCU (SB49.2)
ULPI_D6: USB_OTG_HS_externalPHY (U20.10), MCU (U15.M13)
ULPI_D7: USB_OTG_HS_externalPHY (U20.13), MCU (U15.E7)
ULPI_DIR: USB_OTG_HS_externalPHY (U20.31), MCU (U15.G5)
ULPI_NXT: USB_OTG_HS_externalPHY (U20.2), MCU (U15.M5)
ULPI_STP: USB_OTG_HS_externalPHY (U20.29), MCU (U15.L3)
USB_OTG_HS_OVCR: USB_OTG_HS_externalPHY (LD8.2 R102.1 U25.3), MCU (U15.L11)
uSD_Detect: SDcard (CN4.10 R24.1), MCU (U15.C1)
USER_LED1: Peripherals (R10.2), MCU (U15.B8)
USER_LED2: Peripherals (R4.2), MCU (U15.H13)
WAKEUP: Peripherals (5 pins), MCU (U15.F4)
WIFI_BOOT: Peripherals (U5.39), MCU (U15.A14)
WIFI_DATRDY: Peripherals (SB27.1), MCU (U15.B2)
WIFI_GPIO: Peripherals (SB17.2), MCU (U15.A2)
WIFI_RST: Peripherals (SB16.2), MCU (U15.E11)
WIFI_WKUP: Peripherals (SB14.2), MCU (U15.D12)

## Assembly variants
H7B3I: not fitted C39 C53 C97 C99 C102 C122 CN9 CN12 CN13 CN17 R12 R14 R24 R45 R58 R65 R88 R100 R101 SB2 SB3 SB4 SB5 SB6 SB7 SB8 SB9 SB10 SB11 SB12 SB13 SB15 SB18 SB21 SB23 SB25 SB34 SB35 SB39 SB40 SB42 SB43 SB53 SB55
